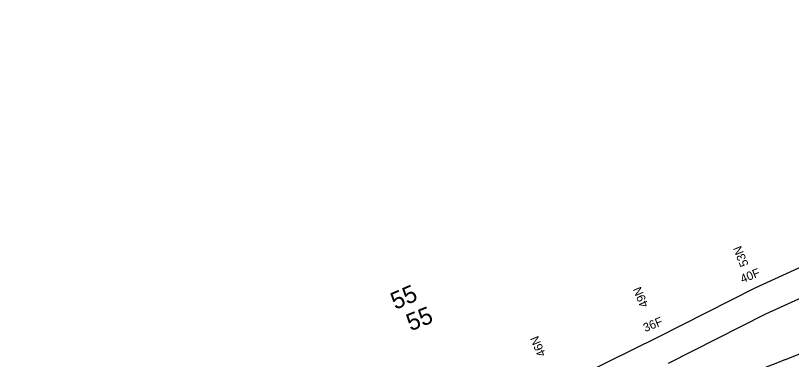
# Model space of a CAD drawing. Extents: x 1964982 to 1970527, y 1116335 to 1119906.
# Drawn here: x 1967005.9 to 1967364.9, y 1117720.4 to 1117879.8 of the extents above; entities that cross this region are included whole.
import ezdxf

# ---------------------------------------------------------------- set-up
doc = ezdxf.new("R2010")
doc.units = 0
for name, color, linetype in [('RD_HC_TX_Rel_Sta50', 7, 'Continuous'), ('RD_HC_TX_Sta50', 7, 'Continuous'), ('RD_PD_CstnLmt', 7, 'Continuous'), ('RD_PD_DR_ErosCtrl', 7, 'Continuous'), ('RD_PD_TX_CstnLmt', 7, 'Continuous'), ('RD_QTY_GR', 7, 'Continuous'), ('RD_TX_Drainage', 7, 'Continuous')]:
    doc.layers.add(name, color=color, linetype=linetype)

msp = doc.modelspace()

# ---------------------------------------------------------------- linework, layer by layer
at = {"layer": 'RD_PD_CstnLmt'}
for p, q in [((1967353.01, 1117741.56), (1967398.49, 1117762.48)), ((1967307.96, 1117718.75), (1967353.01, 1117741.56))]:
    msp.add_line(p, q, dxfattribs=at)
at = {"layer": 'RD_PD_DR_ErosCtrl'}
msp.add_lwpolyline([(1966775.04, 1117473.43), (1966806.92, 1117492.05), (1966850.96, 1117515.75), (1966896.08, 1117536.71), (1966942.4, 1117554.8), (1966988.58, 1117573.31), (1967035.31, 1117591.29), (1967081.07, 1117611.44), (1967122.99, 1117640.22), (1967170.11, 1117657.3), (1967216.32, 1117677.17), (1967257.68, 1117708.44), (1967302.99, 1117730.76), (1967348.14, 1117753.61), (1967393.62, 1117774.54), (1967438.86, 1117796.03), (1967484.63, 1117816.22), (1967530.58, 1117835.95), (1967576.54, 1117855.67), (1967623.7, 1117875.38), (1967630.48, 1117878.02), (1967634.79, 1117879.81)], dxfattribs=at)
at = {"layer": 'RD_QTY_GR'}
msp.add_line((1967362.07, 1117720.41), (1967613.08, 1117821.8), dxfattribs=at)
msp.add_arc((1969514.39, 1112392.12), 5746.58, 111.995838, 113.534115, dxfattribs=at)

# ---------------------------------------------------------------- texts
at = {"layer": 'RD_HC_TX_Rel_Sta50'}
msp.add_text('55', height=8, rotation=23.5006, dxfattribs=at).set_placement((1967181.59, 1117743.33))
at = {"layer": 'RD_HC_TX_Sta50'}
msp.add_text('55', height=8, rotation=21.9958, dxfattribs=at).set_placement((1967188.67, 1117733.42))
at = {"layer": 'RD_PD_TX_CstnLmt'}
for s, rotation, p in [('40F', 22.0006, (1967342.19, 1117755.7)), ('36F', 22.5006, (1967297.21, 1117733.06))]:
    msp.add_text(s, height=4, rotation=rotation, dxfattribs=at).set_placement(p)
at = {"layer": 'RD_TX_Drainage'}
for s, rotation, p in [('53N', 112.0006, (1967345.12, 1117764.34)), ('49N', 112.5006, (1967298.84, 1117745.45)), ('46N', 113.0006, (1967251.35, 1117722.68))]:
    msp.add_text(s, height=4, rotation=rotation, dxfattribs=at).set_placement(p)

doc.saveas('drawing.dxf')
